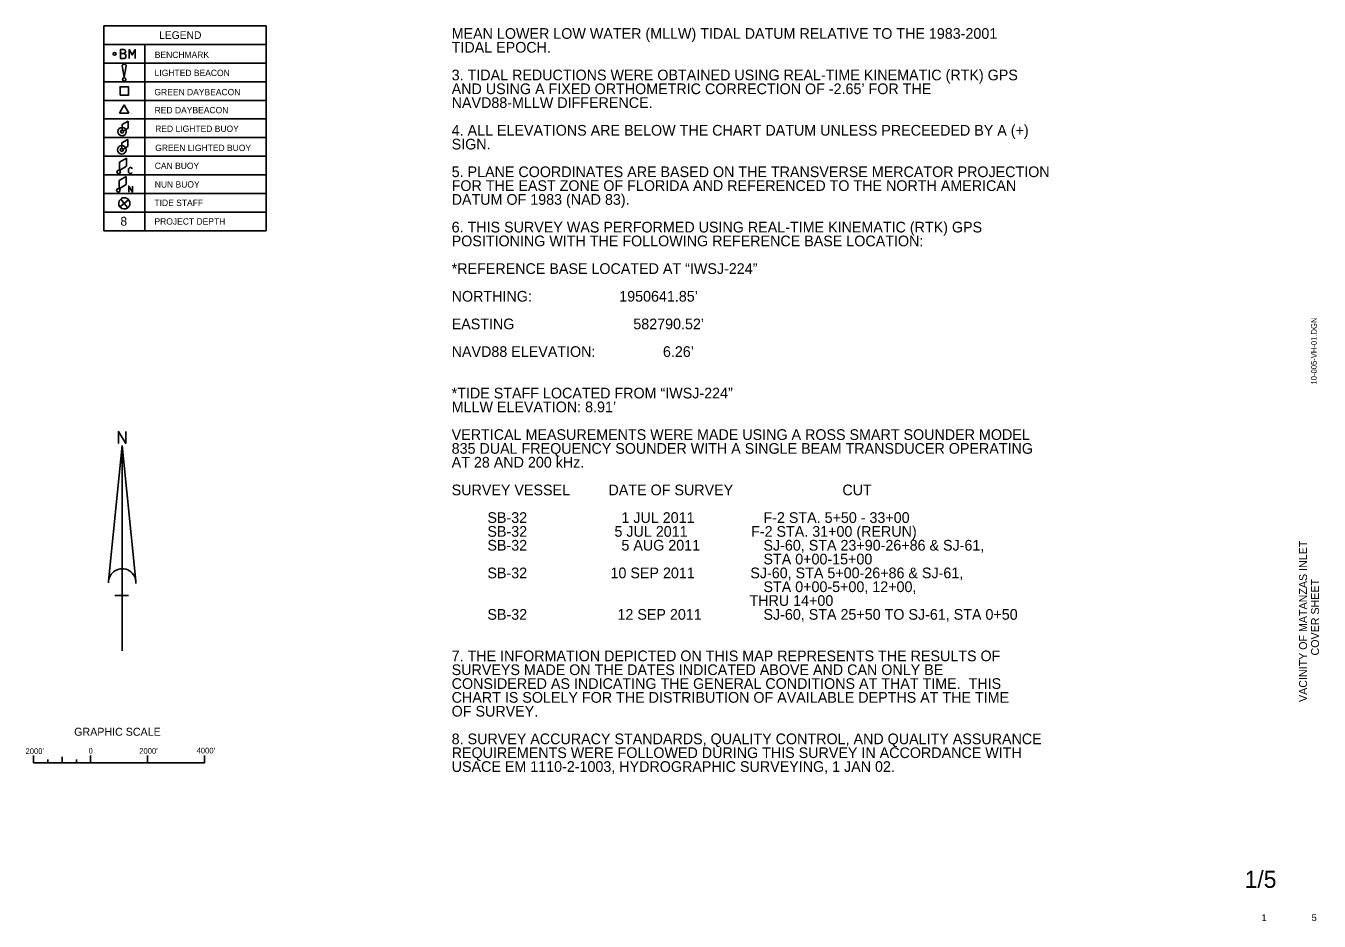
# Model space of a CAD drawing. Extents: x 565003 to 644146, y 1916234 to 1975957.
# Drawn here: x 598767 to 644146, y 1916234 to 1947650 of the extents above; entities that cross this region are included whole.
import ezdxf

# ---------------------------------------------------------------- set-up
doc = ezdxf.new("R2010")
doc.units = 0
for name, color, linetype in [('C-RUNW-THRS', 7, 'Continuous'), ('C-TAXI-CNTR', 7, 'Continuous'), ('C-TAXI-CNTR-IDEN', 7, 'Continuous'), ('C-TAXI-EDGE', 7, 'Continuous')]:
    doc.layers.add(name, color=color, linetype=linetype)

msp = doc.modelspace()

# ---------------------------------------------------------------- linework, layer by layer
at = {"layer": 'C-TAXI-CNTR'}
for p, q in [((601667, 1928169), (602145, 1932920)), ((602145, 1925721), (602145, 1932920)), ((602623, 1928169), (602145, 1932920)), ((602372, 1927665), (601893, 1927665)), ((599039, 1921791), (599039, 1922042)), ((599539, 1921796), (599539, 1921911)), ((600039, 1921791), (600039, 1921995)), ((600039, 1921796), (600039, 1921911)), ((600539, 1921796), (600539, 1921911)), ((601038, 1921791), (601038, 1922041)), ((601038, 1921791), (601038, 1922041)), ((601038, 1921791), (601039, 1921911)), ((603038, 1921791), (603038, 1922041)), ((605038, 1921791), (605038, 1922041)), ((599039, 1921791), (605039, 1921791))]:
    msp.add_line(p, q, dxfattribs=at)
msp.add_lwpolyline([(602012, 1932997), (602012, 1933417), (602274, 1932997), (602274, 1933417)], dxfattribs=at)
msp.add_arc((602145, 1928121), 480, 355.2984, 182.0673, dxfattribs=at)
at = {"layer": 'C-TAXI-EDGE'}
for p, q in [((601500, 1947650), (601500, 1940459)), ((601500, 1947650), (607195, 1947650)), ((607195, 1947650), (607195, 1940459)), ((601500, 1946996), (607195, 1946996)), ((602942, 1946993), (602942, 1940459)), ((601500, 1946342), (607195, 1946342)), ((602220, 1945847), (602150, 1946242)), ((602290, 1946242), (602220, 1945847)), ((601500, 1945689), (607195, 1945689)), ((601500, 1945035), (607195, 1945035)), ((602052, 1944589), (602218, 1944875)), ((602383, 1944588), (602052, 1944589)), ((602218, 1944875), (602382, 1944589)), ((601500, 1944382), (607195, 1944382)), ((602143, 1944184), (602354, 1944306)), ((602143, 1943993), (602143, 1944184)), ((602354, 1944063), (602188, 1943967)), ((602354, 1944306), (602354, 1944063)), ((601500, 1943728), (607195, 1943728)), ((602133, 1943542), (602343, 1943663)), ((602343, 1943663), (602343, 1943420)), ((602133, 1943350), (602133, 1943542)), ((602343, 1943420), (602178, 1943324)), ((601500, 1943074), (607195, 1943074)), ((602052, 1942866), (602303, 1943012)), ((602052, 1942576), (602052, 1942866)), ((602303, 1942722), (602052, 1942576)), ((602303, 1943012), (602303, 1942722)), ((601500, 1942420), (607195, 1942420)), ((602040, 1942223), (602291, 1942367)), ((602291, 1942367), (602290, 1942078)), ((602039, 1941934), (602040, 1942223)), ((602290, 1942078), (602039, 1941934)), ((601500, 1941767), (607195, 1941767)), ((602221, 1941421), (602069, 1941294)), ((602095, 1941573), (602221, 1941421)), ((602221, 1941421), (602374, 1941547)), ((602348, 1941268), (602221, 1941421)), ((601500, 1941113), (607195, 1941113)), ((601500, 1940459), (607195, 1940459))]:
    msp.add_line(p, q, dxfattribs=at)
for points in [[(602222, 1946675), (602249, 1946704), (602262, 1946741), (602262, 1946753), (602249, 1946795), (602207, 1946817), (602082, 1946817), (602082, 1946505), (602222, 1946505), (602262, 1946527), (602276, 1946569), (602276, 1946606), (602262, 1946643), (602222, 1946675), (602082, 1946675)], [(602392, 1946505), (602392, 1946817), (602497, 1946628), (602603, 1946817), (602603, 1946505)], [(602495, 1942634), (602469, 1942669), (602442, 1942676), (602424, 1942676), (602399, 1942669), (602370, 1942634), (602364, 1942588), (602364, 1942563), (602364, 1942546), (602366, 1942531), (602371, 1942504), (602399, 1942471), (602424, 1942465), (602439, 1942465), (602467, 1942471), (602495, 1942505)], [(602375, 1941818), (602376, 1942030), (602506, 1941818), (602507, 1942029)]]:
    msp.add_lwpolyline(points, dxfattribs=at)
msp.add_lwpolyline([(602072, 1945216), (602072, 1945511), (602367, 1945511), (602367, 1945215)], close=True, dxfattribs=at)
for centre, radius in [((601881, 1946665), 48.8), ((602219, 1945771), 59.4), ((602143, 1943941), 148), ((602143, 1943941), 52.1), ((602133, 1943298), 148), ((602133, 1943298), 52.1), ((602023, 1942522), 62), ((602009, 1941879), 62)]:
    msp.add_circle(centre, radius, dxfattribs=at)
for centre, radius, start, end in [((602220, 1946237), 70, 4.6442, 175.3545), ((602221, 1941421), 198, 129.6858, 219.6858), ((602221, 1941421), 198, 39.6856, 129.6858), ((602221, 1941421), 198, 309.6858, 39.6859), ((602221, 1941421), 198, 219.6858, 309.6858)]:
    msp.add_arc(centre, radius, start, end, dxfattribs=at)

# ---------------------------------------------------------------- texts
at = {"layer": 'C-RUNW-THRS'}
for s, height, rotation, p in [('10-005-VH-01.DGN                    ', 200.02, 90, (644065, 1935065)), ('               VACINITY OF MATANZAS INLET              ', 280.03, 90, (643722, 1922364)), ('                      COVER SHEET                      ', 280.03, 90, (644142, 1923267)), (' 1/5  ', 600.1, 360, (641310, 1917402)), (' 1  ', 240, 360, (642036, 1916237)), (' 5  ', 240, 360, (643794, 1916237))]:
    msp.add_text(s, height=height, rotation=rotation, dxfattribs=at).set_placement(p)
at = {"layer": 'C-TAXI-CNTR'}
for s, height, p in [('GRAPHIC SCALE', 279.99, (600462, 1922739)), ("2000'", 200, (598754, 1922097)), ('0', 200, (600967, 1922113)), ("2000'", 200, (602745, 1922106)), ("4000'", 200, (604758, 1922118))]:
    msp.add_text(s, height=height, dxfattribs=at).set_placement(p)
at = {"layer": 'C-TAXI-CNTR-IDEN'}
for s, height, p in [('MEAN LOWER LOW WATER (MLLW) TIDAL DATUM RELATIVE TO THE 1983-2001', 375.02, (613708, 1947195)), ('TIDAL EPOCH.', 375.02, (613708, 1946710)), ('3. TIDAL REDUCTIONS WERE OBTAINED USING REAL-TIME KINEMATIC (RTK) GPS', 375.02, (613708, 1945739)), ('AND USING A FIXED ORTHOMETRIC CORRECTION OF -2.65’ FOR THE ', 375.02, (613708, 1945254)), ('NAVD88-MLLW DIFFERENCE.  ', 375.02, (613708, 1944768)), ('4. ALL ELEVATIONS ARE BELOW THE CHART DATUM UNLESS PRECEEDED BY A (+)', 375.02, (613708, 1943798)), ('SIGN.', 375, (613708, 1943312)), ('5. PLANE COORDINATES ARE BASED ON THE TRANSVERSE MERCATOR PROJECTION', 375.02, (613708, 1942342)), ('FOR THE EAST ZONE OF FLORIDA AND REFERENCED TO THE NORTH AMERICAN', 375.02, (613708, 1941856)), ('DATUM OF 1983 (NAD 83).', 375.02, (613708, 1941371)), ('6. THIS SURVEY WAS PERFORMED USING REAL-TIME KINEMATIC (RTK) GPS', 375.02, (613708, 1940400)), ('POSITIONING WITH THE FOLLOWING REFERENCE BASE LOCATION:', 375.02, (613708, 1939915)), ('*REFERENCE BASE LOCATED AT “IWSJ-224”', 375.02, (613708, 1938944)), ('NORTHING:                      1950641.85’', 375.02, (613708, 1937973)), ('EASTING       ', 375.02, (613708, 1937003)), ('582790.52’', 375, (620082, 1937003)), ('NAVD88 ELEVATION:                 6.26’', 375.02, (613708, 1936032)), ('*TIDE STAFF LOCATED FROM “IWSJ-224”', 375.02, (613708, 1934576)), ('MLLW ELEVATION: 8.91’', 375.02, (613708, 1934091)), ('VERTICAL MEASUREMENTS WERE MADE USING A ROSS SMART SOUNDER MODEL', 375.02, (613708, 1933120)), ('835 DUAL FREQUENCY SOUNDER WITH A SINGLE BEAM TRANSDUCER OPERATING', 375.02, (613708, 1932634)), ('AT 28 AND 200 kHz.', 375.02, (613708, 1932149)), ('SURVEY VESSEL', 375.02, (613708, 1931178)), ('DATE OF SURVEY', 375.02, (619212, 1931178)), ('CUT', 375, (627418, 1931178)), ('         SB-32 ', 375.02, (613708, 1930208)), ('    1 JUL 2011', 375.02, (619108, 1930208)), (' F-2 STA. 5+50 - 33+00', 375.02, (624509, 1930208)), ('         SB-32                      5 JUL 2011                F-2 STA. 31+00 (RERUN)', 375.02, (613708, 1929722)), ('         SB-32 ', 375.02, (613708, 1929237)), ('    5 AUG 2011', 375.02, (619108, 1929237)), (' SJ-60, STA 23+90-26+86 & SJ-61, ', 375.02, (624509, 1929237)), (' STA 0+00-15+00', 375.02, (624509, 1928752)), ('         SB-32                     10 SEP 2011              SJ-60, STA 5+00-26+86 & SJ-61, ', 375.02, (613708, 1928266)), (' STA 0+00-5+00, 12+00,                ', 375.02, (624509, 1927781)), ('                                                                           THRU 14+00', 375.02, (613708, 1927296)), ('         SB-32 ', 375.02, (613708, 1926810)), ('   12 SEP 2011', 375.02, (619108, 1926810)), (' SJ-60, STA 25+50 TO SJ-61, STA 0+50', 375.02, (624509, 1926810)), ('7. THE INFORMATION DEPICTED ON THIS MAP REPRESENTS THE RESULTS OF ', 375.02, (613708, 1925354)), ('SURVEYS MADE ON THE DATES INDICATED ABOVE AND CAN ONLY BE', 375.02, (613708, 1924869)), ('CONSIDERED AS INDICATING THE GENERAL CONDITIONS AT THAT TIME.  THIS', 375.02, (613708, 1924383)), ('CHART IS SOLELY FOR THE DISTRIBUTION OF AVAILABLE DEPTHS AT THE TIME', 375.02, (613708, 1923898)), ('OF SURVEY.', 375, (613708, 1923413)), ('8. SURVEY ACCURACY STANDARDS, QUALITY CONTROL, AND QUALITY ASSURANCE', 375.02, (613708, 1922442)), ('REQUIREMENTS WERE FOLLOWED DURING THIS SURVEY IN ACCORDANCE WITH', 375.02, (613708, 1921957)), ('USACE EM 1110-2-1003, HYDROGRAPHIC SURVEYING, 1 JAN 02.  ', 375.02, (613708, 1921471))]:
    msp.add_text(s, height=height, dxfattribs=at).set_placement(p)
at = {"layer": 'C-TAXI-EDGE'}
for s, height, p in [('LEGEND', 270.4, (603441, 1947190)), ('BENCHMARK', 223.1, (603290, 1946524)), ('LIGHTED BEACON', 223.1, (603286, 1945887)), ('GREEN DAYBEACON', 223.1, (603277, 1945215)), ('RED DAYBEACON', 223.1, (603286, 1944582)), ('RED LIGHTED BUOY', 223.1, (603305, 1943929)), ('GREEN LIGHTED BUOY', 223.1, (603305, 1943257)), ('CAN BUOY', 223.1, (603290, 1942628)), ('NUN BUOY', 223.1, (603290, 1941975)), ('TIDE STAFF', 223.1, (603279, 1941329)), ('8', 313, (602086, 1940637)), ('PROJECT DEPTH', 223.1, (603279, 1940676))]:
    msp.add_text(s, height=height, rotation=360, dxfattribs=at).set_placement(p)

doc.saveas('drawing.dxf')
